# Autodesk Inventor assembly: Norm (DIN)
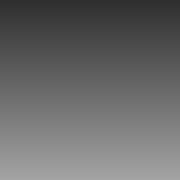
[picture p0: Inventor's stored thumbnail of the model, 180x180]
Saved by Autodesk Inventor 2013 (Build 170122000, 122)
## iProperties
Shininess: 64.0
Length Units: 11269
Angle Units: 11279
Time Units: 11290
Mass Units: 11283
Length Display Precision: 3
Angle Display Precision: 2
Compacted: True
Created: 2002-07
Part Number: Norm (DIN)
Document SubType Name: Assembly
Density: 0.0
Volumn: 0.0
Area: 0.0
PropertySet Name: Model Information
Control State: 0
Master: False
Checked Out: False
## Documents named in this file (1)
- C:\Users\wade\Desktop\MMM\Norm (DIN).iam
